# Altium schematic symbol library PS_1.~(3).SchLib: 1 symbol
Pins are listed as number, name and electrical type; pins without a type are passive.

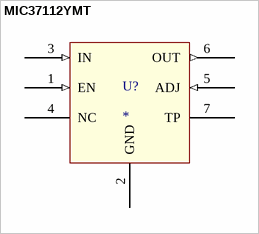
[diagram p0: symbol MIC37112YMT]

## MIC37112YMT
designator U?
LDO, 1A
pins: 1 EN (in), 2 GND (power), 3 IN (in), 4 NC (power), 5 ADJ (in), 6 OUT (out), 7 TP (power)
